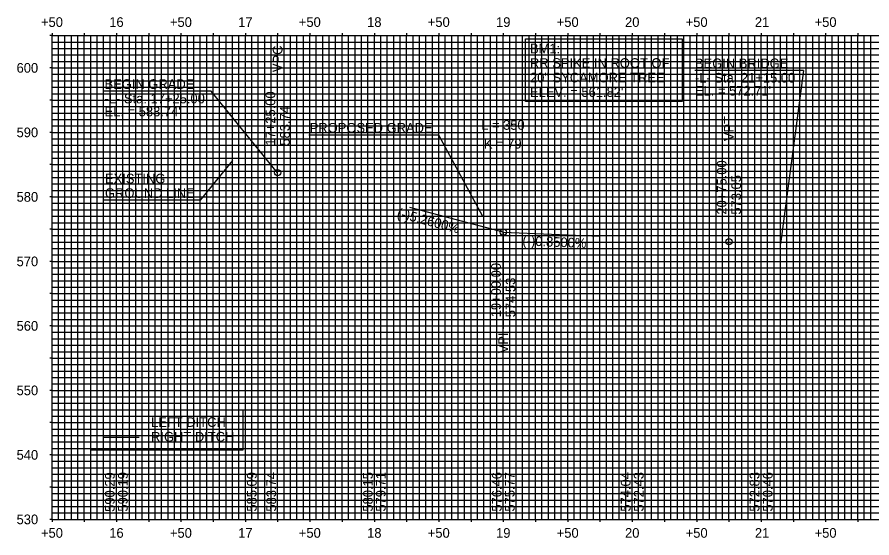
# Model space of a CAD drawing. Extents: x 523 to 1977, y 516 to 919.
# Drawn here: x 523 to 1186, y 516 to 919 of the extents above; entities that cross this region are included whole.
import ezdxf

# ---------------------------------------------------------------- set-up
doc = ezdxf.new("R2010")
doc.units = 0
for name, color, linetype in [('E_ENV_WETLAND_BOUNDARY', 7, 'Continuous'), ('E_NCDOT_Vertical_Profile_Ground_Line', 7, 'Continuous'), ('Exist Hydro Jurisdictional Stream or Body of Water', 7, 'Continuous'), ('P_HYD_False_Sump_3_Detail_CELL', 7, 'Continuous'), ('P_NCDOT_Horizontal_Alignment_Curve_and_Spiral_Data', 7, 'Continuous'), ('P_NCDOT_Horizontal_Alignment_Direction_Label', 7, 'Continuous'), ('P_NCDOT_Horizontal_Alignment_Station_Label', 7, 'Continuous'), ('P_NCDOT_Intersecting_Profile', 7, 'Continuous'), ('P_NCDOT_Vertical_Profile_Grade', 7, 'Continuous'), ('P_NCDOT_VPI_Ditch_Grade_Left_Label', 7, 'Continuous'), ('Prop VPI Ditch Grade Right Label', 7, 'Continuous'), ('Scratch_Level_2', 7, 'Continuous'), ('Scratch_Level_4', 7, 'Continuous'), ('Sheet_Sticker_Incomplete_CELL', 7, 'Continuous')]:
    doc.layers.add(name, color=color, linetype=linetype)

msp = doc.modelspace()

# ---------------------------------------------------------------- linework, layer by layer
at = {"layer": 'E_ENV_WETLAND_BOUNDARY'}
for p, q in [((1132.86, 877.91), (1048.48, 877.91)), ((1132.86, 877.91), (1114.95, 743.54)), ((725, 798.7), (725, 873.7)), ((673.35, 861.82), (590, 861.82)), ((725, 798.7), (673.35, 861.82)), ((850, 827.94), (749.14, 827.94)), ((884.14, 764.82), (850, 827.94)), ((1075, 745.24), (1075, 820.24)), ((690, 808.1), (664.99, 777.54)), ((725, 798.7), (725, 798.7)), ((664.99, 777.54), (590, 777.54)), ((900, 752.67), (827.47, 771.75)), ((900, 752.67), (900, 752.67)), ((900, 752.67), (974.93, 749.49)), ((900, 752.67), (900, 677.67)), ((1075, 745.24), (1075, 745.24))]:
    msp.add_line(p, q, dxfattribs=at)
for points in [[(917.33, 902.44), (1038.72, 902.44), (1038.72, 853.86), (917.33, 853.86)], [(580.23, 615), (697.98, 615), (697.98, 583.73), (580.23, 583.73)]]:
    msp.add_lwpolyline(points, close=True, dxfattribs=at)
for centre in [(725, 798.7), (900, 752.67), (1075, 745.24)]:
    msp.add_circle(centre, 2.43, dxfattribs=at)
at = {"layer": 'E_NCDOT_Vertical_Profile_Ground_Line'}
for p, q in [((600, 530), (600, 905)), ((650, 530), (650, 905)), ((700, 530), (700, 905)), ((750, 530), (750, 905)), ((800, 530), (800, 905)), ((850, 530), (850, 905)), ((900, 530), (900, 905)), ((950, 530), (950, 905)), ((1000, 530), (1000, 905)), ((1050, 530), (1050, 905)), ((1100, 530), (1100, 905)), ((1150, 530), (1150, 905)), ((550, 880), (1950, 880)), ((550, 830), (1950, 830)), ((550, 780), (1950, 780)), ((550, 730), (1950, 730)), ((550, 680), (1950, 680)), ((550, 630), (1950, 630)), ((550, 580), (1950, 580))]:
    msp.add_line(p, q, dxfattribs=at)
at = {"layer": 'P_HYD_False_Sump_3_Detail_CELL'}
msp.add_line((589.52, 605.04), (617.65, 605.04), dxfattribs=at)
at = {"layer": 'P_NCDOT_Horizontal_Alignment_Curve_and_Spiral_Data'}
for p, q in [((555, 530), (555, 905)), ((560, 530), (560, 905)), ((565, 530), (565, 905)), ((570, 530), (570, 905)), ((580, 530), (580, 905)), ((585, 530), (585, 905)), ((590, 530), (590, 905)), ((595, 530), (595, 905)), ((605, 530), (605, 905)), ((610, 530), (610, 905)), ((615, 530), (615, 905)), ((620, 530), (620, 905)), ((630, 530), (630, 905)), ((635, 530), (635, 905)), ((640, 530), (640, 905)), ((645, 530), (645, 905)), ((655, 530), (655, 905)), ((660, 530), (660, 905)), ((665, 530), (665, 905)), ((670, 530), (670, 905)), ((680, 530), (680, 905)), ((685, 530), (685, 905)), ((690, 530), (690, 905)), ((695, 530), (695, 905)), ((705, 530), (705, 905)), ((710, 530), (710, 905)), ((715, 530), (715, 905)), ((720, 530), (720, 905)), ((730, 530), (730, 905)), ((735, 530), (735, 905)), ((740, 530), (740, 905)), ((745, 530), (745, 905)), ((755, 530), (755, 905)), ((760, 530), (760, 905)), ((765, 530), (765, 905)), ((770, 530), (770, 905)), ((780, 530), (780, 905)), ((785, 530), (785, 905)), ((790, 530), (790, 905)), ((795, 530), (795, 905)), ((805, 530), (805, 905)), ((810, 530), (810, 905)), ((815, 530), (815, 905)), ((820, 530), (820, 905)), ((830, 530), (830, 905)), ((835, 530), (835, 905)), ((840, 530), (840, 905)), ((845, 530), (845, 905)), ((855, 530), (855, 905)), ((860, 530), (860, 905)), ((865, 530), (865, 905)), ((870, 530), (870, 905)), ((880, 530), (880, 905)), ((885, 530), (885, 905)), ((890, 530), (890, 905)), ((895, 530), (895, 905)), ((905, 530), (905, 905)), ((910, 530), (910, 905)), ((915, 530), (915, 905)), ((920, 530), (920, 905)), ((930, 530), (930, 905)), ((935, 530), (935, 905)), ((940, 530), (940, 905)), ((945, 530), (945, 905)), ((955, 530), (955, 905)), ((960, 530), (960, 905)), ((965, 530), (965, 905)), ((970, 530), (970, 905)), ((980, 530), (980, 905)), ((985, 530), (985, 905)), ((990, 530), (990, 905)), ((995, 530), (995, 905)), ((1005, 530), (1005, 905)), ((1010, 530), (1010, 905)), ((1015, 530), (1015, 905)), ((1020, 530), (1020, 905)), ((1030, 530), (1030, 905)), ((1035, 530), (1035, 905)), ((1040, 530), (1040, 905)), ((1045, 530), (1045, 905)), ((1055, 530), (1055, 905)), ((1060, 530), (1060, 905)), ((1065, 530), (1065, 905)), ((1070, 530), (1070, 905)), ((1080, 530), (1080, 905)), ((1085, 530), (1085, 905)), ((1090, 530), (1090, 905)), ((1095, 530), (1095, 905)), ((1105, 530), (1105, 905)), ((1110, 530), (1110, 905)), ((1115, 530), (1115, 905)), ((1120, 530), (1120, 905)), ((1130, 530), (1130, 905)), ((1135, 530), (1135, 905)), ((1140, 530), (1140, 905)), ((1145, 530), (1145, 905)), ((1155, 530), (1155, 905)), ((1160, 530), (1160, 905)), ((1165, 530), (1165, 905)), ((1170, 530), (1170, 905)), ((1180, 530), (1180, 905)), ((1185, 530), (1185, 905)), ((550, 900), (1950, 900)), ((550, 895), (1950, 895)), ((550, 890), (1950, 890)), ((550, 885), (1950, 885)), ((550, 875), (1950, 875)), ((550, 870), (1950, 870)), ((550, 865), (1950, 865)), ((550, 860), (1950, 860)), ((550, 850), (1950, 850)), ((550, 845), (1950, 845)), ((550, 840), (1950, 840)), ((550, 835), (1950, 835)), ((550, 825), (1950, 825)), ((550, 820), (1950, 820)), ((550, 815), (1950, 815)), ((550, 810), (1950, 810)), ((550, 800), (1950, 800)), ((550, 795), (1950, 795)), ((550, 790), (1950, 790)), ((550, 785), (1950, 785)), ((550, 775), (1950, 775)), ((550, 770), (1950, 770)), ((550, 765), (1950, 765)), ((550, 760), (1950, 760)), ((550, 750), (1950, 750)), ((550, 745), (1950, 745)), ((550, 740), (1950, 740)), ((550, 735), (1950, 735)), ((550, 725), (1950, 725)), ((550, 720), (1950, 720)), ((550, 715), (1950, 715)), ((550, 710), (1950, 710)), ((550, 700), (1950, 700)), ((550, 695), (1950, 695)), ((550, 690), (1950, 690)), ((550, 685), (1950, 685)), ((550, 675), (1950, 675)), ((550, 670), (1950, 670)), ((550, 665), (1950, 665)), ((550, 660), (1950, 660)), ((550, 650), (1950, 650)), ((550, 645), (1950, 645)), ((550, 640), (1950, 640)), ((550, 635), (1950, 635)), ((550, 625), (1950, 625)), ((550, 620), (1950, 620)), ((550, 615), (1950, 615)), ((550, 610), (1950, 610)), ((550, 600), (1950, 600)), ((550, 595), (1950, 595)), ((550, 590), (1950, 590)), ((550, 585), (1950, 585)), ((550, 575), (1950, 575)), ((550, 570), (1950, 570)), ((550, 565), (1950, 565)), ((550, 560), (1950, 560)), ((550, 550), (1950, 550)), ((550, 545), (1950, 545)), ((550, 540), (1950, 540)), ((550, 535), (1950, 535))]:
    msp.add_line(p, q, dxfattribs=at)
at = {"layer": 'P_NCDOT_Horizontal_Alignment_Direction_Label'}
for p, q in [((550, 905), (548.2, 905)), ((550, 906.8), (550, 905)), ((575, 906.8), (575, 905)), ((575, 530), (575, 905)), ((600, 906.8), (600, 905)), ((600, 530), (600, 905)), ((625, 906.8), (625, 905)), ((625, 530), (625, 905)), ((650, 906.8), (650, 905)), ((650, 530), (650, 905)), ((675, 906.8), (675, 905)), ((675, 530), (675, 905)), ((700, 906.8), (700, 905)), ((700, 530), (700, 905)), ((725, 906.8), (725, 905)), ((725, 530), (725, 905)), ((750, 906.8), (750, 905)), ((750, 530), (750, 905)), ((775, 906.8), (775, 905)), ((775, 530), (775, 905)), ((800, 906.8), (800, 905)), ((800, 530), (800, 905)), ((825, 906.8), (825, 905)), ((825, 530), (825, 905)), ((850, 906.8), (850, 905)), ((850, 530), (850, 905)), ((875, 906.8), (875, 905)), ((875, 530), (875, 905)), ((900, 906.8), (900, 905)), ((900, 530), (900, 905)), ((925, 906.8), (925, 905)), ((925, 530), (925, 905)), ((950, 906.8), (950, 905)), ((950, 530), (950, 905)), ((975, 906.8), (975, 905)), ((975, 530), (975, 905)), ((1000, 906.8), (1000, 905)), ((1000, 530), (1000, 905)), ((1025, 906.8), (1025, 905)), ((1025, 530), (1025, 905)), ((1050, 906.8), (1050, 905)), ((1050, 530), (1050, 905)), ((1075, 906.8), (1075, 905)), ((1075, 530), (1075, 905)), ((1100, 906.8), (1100, 905)), ((1100, 530), (1100, 905)), ((1125, 906.8), (1125, 905)), ((1125, 530), (1125, 905)), ((1150, 906.8), (1150, 905)), ((1150, 530), (1150, 905)), ((1175, 906.8), (1175, 905)), ((1175, 530), (1175, 905)), ((550, 880), (548.2, 880)), ((550, 880), (1950, 880)), ((550, 855), (548.2, 855)), ((550, 855), (1950, 855)), ((550, 830), (548.2, 830)), ((550, 830), (1950, 830)), ((550, 805), (548.2, 805)), ((550, 805), (1950, 805)), ((550, 780), (548.2, 780)), ((550, 780), (1950, 780)), ((550, 755), (548.2, 755)), ((550, 755), (1950, 755)), ((550, 730), (548.2, 730)), ((550, 730), (1950, 730)), ((550, 705), (548.2, 705)), ((550, 705), (1950, 705)), ((550, 680), (548.2, 680)), ((550, 680), (1950, 680)), ((550, 655), (548.2, 655)), ((550, 655), (1950, 655)), ((550, 630), (548.2, 630)), ((550, 630), (1950, 630)), ((550, 605), (548.2, 605)), ((550, 605), (1950, 605)), ((550, 580), (548.2, 580)), ((550, 580), (1950, 580)), ((550, 555), (548.2, 555)), ((550, 555), (1950, 555)), ((550, 530), (548.2, 530)), ((550, 530), (550, 528.2)), ((575, 530), (575, 528.2)), ((600, 530), (600, 528.2)), ((625, 530), (625, 528.2)), ((650, 530), (650, 528.2)), ((675, 530), (675, 528.2)), ((700, 530), (700, 528.2)), ((725, 530), (725, 528.2)), ((750, 530), (750, 528.2)), ((775, 530), (775, 528.2)), ((800, 530), (800, 528.2)), ((825, 530), (825, 528.2)), ((850, 530), (850, 528.2)), ((875, 530), (875, 528.2)), ((900, 530), (900, 528.2)), ((925, 530), (925, 528.2)), ((950, 530), (950, 528.2)), ((975, 530), (975, 528.2)), ((1000, 530), (1000, 528.2)), ((1025, 530), (1025, 528.2)), ((1050, 530), (1050, 528.2)), ((1075, 530), (1075, 528.2)), ((1100, 530), (1100, 528.2)), ((1125, 530), (1125, 528.2)), ((1150, 530), (1150, 528.2)), ((1175, 530), (1175, 528.2))]:
    msp.add_line(p, q, dxfattribs=at)
at = {"layer": 'P_NCDOT_Horizontal_Alignment_Station_Label'}
for p, q in [((550, 905), (1950, 905)), ((550, 530), (550, 905)), ((550, 530), (1950, 530))]:
    msp.add_line(p, q, dxfattribs=at)
at = {"layer": 'Prop VPI Ditch Grade Right Label'}
msp.add_line((589.52, 593.63), (617.65, 593.63), dxfattribs=at)
at = {"layer": 'Sheet_Sticker_Incomplete_CELL'}
msp.add_circle((725, 583.74), 0.05, dxfattribs=at)

# ---------------------------------------------------------------- texts
at = {"layer": 'E_ENV_WETLAND_BOUNDARY'}
for s, rotation, p in [('VPC', 90, (728.75, 876.7)), ('BEGIN BRIDGE', 360, (1048.64, 879.76)), ('-L- Sta. 21+15.00', 360, (1048.64, 868.6)), ('BEGIN GRADE', 360, (590.76, 863.67)), ("EL. = 572.71'", 360, (1048.64, 858.54)), ('-L- Sta. 17+25.00', 360, (590.76, 852.5)), ('17+25.00', 90, (723.12, 819.7)), ("EL. = 583.74'", 360, (590.76, 842.44)), ('583.74', 90, (734.37, 819.7)), ('VPT', 90, (1078.75, 823.24)), ('PROPOSED GRADE', 360, (749.9, 829.79)), ('20+75.00', 90, (1073.12, 766.24)), ('573.05', 90, (1084.37, 766.24)), ('(-)5.2600%', 345.2649, (817.05, 764.25)), ('(-)0.8500%', 357.56639, (914.71, 742.42)), ('19+00.00', 90, (898.12, 686.67)), ('574.53', 90, (909.37, 686.67)), ('VPI', 90, (903.75, 658.72))]:
    msp.add_text(s, height=7.5, rotation=rotation, dxfattribs=at).set_placement(p)
for s, p in [('BM1:', (920.72, 891.25)), ('RR SPIKE IN ROOT OF', (920.72, 880)), ('20" SYCAMORE TREE', (920.72, 868.75)), ("ELEV. = 561.82'", (920.72, 857.5)), ('EXISTING', (591.12, 790.44)), ('GROUND LINE', (591.12, 779.19))]:
    msp.add_text(s, height=7.5, dxfattribs=at).set_placement(p)
at = {"layer": 'Exist Hydro Jurisdictional Stream or Body of Water'}
for s, p in [('590.29', (598.6, 535.83)), ('590.19', (608.72, 536)), ('585.09', (708.68, 536)), ('579.71', (808.75, 536)), ('575.77', (908.77, 536)), ('572.43', (1008.8, 536)), ('570.46', (1108.84, 536))]:
    msp.add_text(s, height=7.5, rotation=90, dxfattribs=at).set_placement(p)
at = {"layer": 'P_NCDOT_Intersecting_Profile'}
for s, p in [('L = 350', (882.83, 832)), ('K = 79', (884.94, 817.5))]:
    msp.add_text(s, height=7.5, dxfattribs=at).set_placement(p)
at = {"layer": 'P_NCDOT_Vertical_Profile_Grade'}
for s, p in [('+50', (541.46, 911.75)), ('16', (594.41, 911.75)), ('+50', (641.46, 911.75)), ('17', (694.41, 911.75)), ('+50', (741.46, 911.75)), ('18', (794.41, 911.75)), ('+50', (841.46, 911.75)), ('19', (894.41, 911.75)), ('+50', (941.46, 911.75)), ('20', (994.43, 911.75)), ('+50', (1041.46, 911.75)), ('21', (1095.14, 911.75)), ('+50', (1141.46, 911.75)), ('+50', (541.46, 515.75)), ('16', (594.41, 515.75)), ('+50', (641.46, 515.75)), ('17', (694.41, 515.75)), ('+50', (741.46, 515.75)), ('18', (794.41, 515.75)), ('+50', (841.46, 515.75)), ('19', (894.41, 515.75)), ('+50', (941.46, 515.75)), ('20', (994.43, 515.75)), ('+50', (1041.46, 515.75)), ('21', (1095.14, 515.75)), ('+50', (1141.46, 515.75))]:
    msp.add_text(s, height=7.5, dxfattribs=at).set_placement(p)
at = {"layer": 'P_NCDOT_VPI_Ditch_Grade_Left_Label'}
msp.add_text('LEFT DITCH', height=7.5, dxfattribs=at).set_placement((626.85, 601.68))
at = {"layer": 'Prop VPI Ditch Grade Right Label'}
msp.add_text('RIGHT DITCH', height=7.5, dxfattribs=at).set_placement((626.85, 590.31))
at = {"layer": 'Scratch_Level_2'}
for s, p in [('600', (522.53, 876.25)), ('590', (522.53, 826.25)), ('580', (522.53, 776.25)), ('570', (522.53, 726.25)), ('560', (522.53, 676.25)), ('550', (522.53, 626.25)), ('540', (522.53, 576.25)), ('530', (522.53, 526.25))]:
    msp.add_text(s, height=7.5, dxfattribs=at).set_placement(p)
at = {"layer": 'Scratch_Level_4'}
for s, p in [('583.74', (723.82, 536)), ('580.15', (798.76, 536)), ('576.46', (898.71, 536)), ('574.04', (998.67, 536)), ('572.83', (1098.65, 536))]:
    msp.add_text(s, height=7.5, rotation=90, dxfattribs=at).set_placement(p)

doc.saveas('drawing.dxf')
